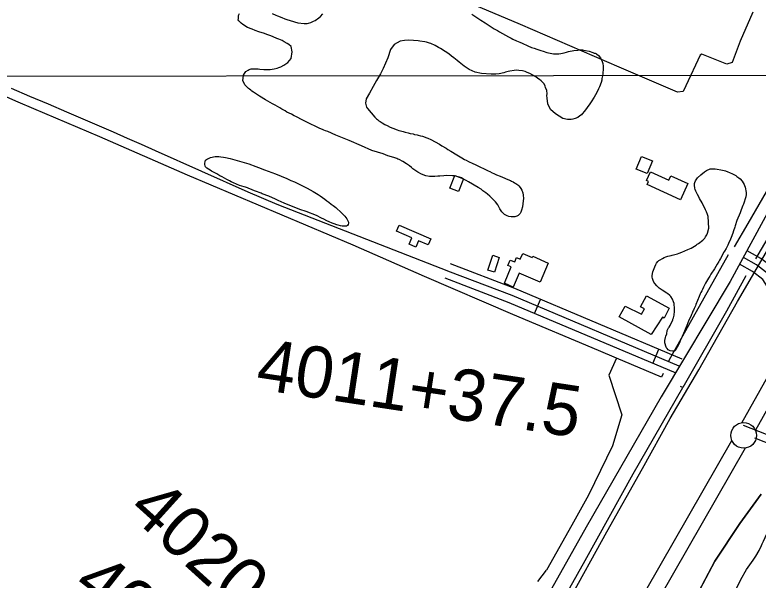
# Model space of a CAD drawing. Extents: x 3297735 to 3335592, y 670436 to 695807.
# Drawn here: x 3313752 to 3315202, y 689991 to 691094 of the extents above; entities that cross this region are included whole.
import ezdxf

# ---------------------------------------------------------------- set-up
doc = ezdxf.new("R2010")
doc.units = 0
for name, color, linetype in [('V-BLDG-OTLN', 7, 'Continuous'), ('V-DTCH-CNTR', 7, 'Continuous'), ('V-GRID-MAJR', 7, 'Continuous'), ('V-LEVE-TOET', 7, 'Continuous'), ('V-ROAD-CNTR', 7, 'Continuous'), ('V-SITE-VEGE', 7, 'Continuous'), ('V-SURV-IDEN', 7, 'Continuous'), ('V-SURV-LINE', 7, 'Continuous'), ('V-TOPO-SHOR', 7, 'Continuous'), ('V-WETL-SWMP', 7, 'Continuous')]:
    doc.layers.add(name, color=color, linetype=linetype)

msp = doc.modelspace()

# ---------------------------------------------------------------- linework, layer by layer
at = {"layer": 'V-BLDG-OTLN'}
for points in [[(3314964.3, 690793.1), (3314974.4, 690817.9), (3314995.9, 690809.1), (3314985.8, 690784.3)], [(3314627.4, 690773.9), (3314617.7, 690749.5), (3314600.7, 690756.2), (3314610.4, 690780.6)], [(3315050.6, 690733.5), (3314985.4, 690763), (3314988.1, 690768.8), (3314984.1, 690770.6), (3314992, 690788.1), (3315027.8, 690771.8), (3315031.5, 690780), (3315064.8, 690764.9)], [(3314501.7, 690683.8), (3314563.7, 690657.1), (3314558.6, 690645.2), (3314539.6, 690653.3), (3314534.4, 690641), (3314521, 690646.8), (3314526.3, 690659), (3314496.6, 690671.8)], [(3314674.8, 690595.8), (3314684.2, 690625), (3314696.7, 690621), (3314687.4, 690591.8)], [(3314792.4, 690609.9), (3314776.8, 690572.9), (3314735.7, 690590.2), (3314724.3, 690563.1), (3314707, 690570.4), (3314720.5, 690602.5), (3314713.9, 690605.3), (3314718.4, 690615.8), (3314727.2, 690612), (3314730.9, 690620.8), (3314738, 690617.7), (3314742.7, 690628.6), (3314761, 690620.8), (3314762.2, 690623.6)], [(3314993.6, 690470.7), (3314931.1, 690505), (3314942.4, 690526), (3314974.7, 690509.9), (3314980.5, 690520.5), (3314972.7, 690524.6), (3314984.4, 690546), (3315028.6, 690522), (3315018.6, 690502.6), (3315015.2, 690504.3)]]:
    msp.add_lwpolyline(points, close=True, dxfattribs=at)
at = {"layer": 'V-DTCH-CNTR'}
for points in [[(3314925.9, 690424.1), (3314910.5, 690391.2), (3314935.8, 690313.8), (3314918.1, 690253.3), (3314870.9, 690157.4), (3314838.3, 690098.4), (3314789, 690010.9)], [(3314772.2, 689988.7), (3314789, 690010.9)]]:
    msp.add_lwpolyline(points, dxfattribs=at)
at = {"layer": 'V-GRID-MAJR'}
msp.add_lwpolyline([(3301853.1, 690965.8), (3302673.5, 690966.2), (3305673.7, 690968.2), (3310110.3, 690971.5), (3313525.5, 690974.4), (3317355.7, 690978.1), (3321058.1, 690982), (3323164.5, 690984.4), (3326643.7, 690988.7), (3330122.8, 690993.3), (3332835.9, 690997.1), (3333379.4, 690997.9)], dxfattribs=at)
at = {"layer": 'V-LEVE-TOET'}
for points in [[(3314907.1, 690085.8), (3314976.7, 690209.3), (3315030.4, 690306.7), (3315086.4, 690401.8), (3315161.6, 690535), (3315227.4, 690647.1), (3315287.9, 690759.3), (3315343.6, 690858.4), (3315397.6, 690945.4), (3315463.7, 691059.5), (3315520.4, 691145.2), (3315573.3, 691212.4), (3315648.7, 691305.4), (3315744.4, 691421.5), (3315825.6, 691528.8), (3315860, 691571.4)], [(3315207.9, 690159.2), (3315166.1, 690101.6), (3315117.4, 690028.3)], [(3314100.4, 689022.4), (3314111.6, 689037.4), (3314125.1, 689067.9), (3314153.7, 689108.7), (3314193.6, 689148.5), (3314273.3, 689221.9), (3314369, 689302.1), (3314457.5, 689375.3), (3314528.4, 689444.5), (3314572, 689497.3), (3314613.1, 689559.8), (3314664.2, 689653.7), (3314725.2, 689763.3), (3314783.5, 689866.7), (3314830.9, 689947.5), (3314907.1, 690085.8)], [(3315117.4, 690028.3), (3315058.4, 689916.5), (3314990.5, 689797), (3314920.8, 689673.1), (3314848.5, 689549.2), (3314768.2, 689413.2), (3314704.3, 689329.4), (3314636.1, 689250), (3314540.5, 689150), (3314446.3, 689084), (3314346.7, 689010.3), (3314299.8, 688961.1), (3314258, 688900.6), (3314223.3, 688846.9), (3314181.3, 688776.8), (3314158.1, 688736.1), (3314134.7, 688678.8), (3314082.7, 688587.9)]]:
    msp.add_lwpolyline(points, dxfattribs=at)
at = {"layer": 'V-ROAD-CNTR'}
for p, q in [((3314766, 690511.4), (3314777.7, 690539)), ((3314996.3, 690414.2), (3315008, 690441.9))]:
    msp.add_line(p, q, dxfattribs=at)
for points in [[(3314598.5, 690593.7), (3314263.8, 690724), (3314207, 690748.3), (3314026.3, 690828.8), (3313999.1, 690840.9), (3313971.9, 690852.9), (3313944.6, 690864.9), (3313917.2, 690876.7), (3313889.8, 690888.4), (3313853.8, 690904.1), (3313817.7, 690919.6), (3313781.6, 690935), (3313745.4, 690950.2)], [(3315256.1, 690773.3), (3315147.7, 690573.9), (3315012.5, 690349.2), (3314866.5, 690094.8), (3314702, 689802.1)], [(3315284.2, 690514.2), (3315282.2, 690518.3), (3315265.2, 690548), (3315253.6, 690567), (3315233.7, 690598.5), (3315207.4, 690618.7), (3315180.6, 690633.9)], [(3315277.4, 690494), (3315268.9, 690511.3), (3315252.3, 690540.4), (3315240.9, 690559.1), (3315222.5, 690588.3), (3315199.1, 690606.2), (3315173.2, 690620.9)], [(3315054.1, 690422.4), (3314727.5, 690560.2), (3314602, 690608.3)], [(3315264, 690487.4), (3315255.7, 690504.2), (3315239.4, 690532.8), (3315228.1, 690551.2), (3315211.2, 690578), (3315190.8, 690593.7), (3315165.8, 690607.8)], [(3315048.2, 690408.6), (3314721.9, 690546.3), (3314596.6, 690594.3)], [(3315042.4, 690394.8), (3314716.3, 690532.4), (3314591.2, 690580.3)], [(3316183.2, 689553.8), (3315934.9, 689765.3), (3315796.5, 689871.4), (3315695.2, 689937.6), (3315638.5, 689975.3), (3315597.6, 689993.4), (3315531.1, 690029.3), (3315471.3, 690048.8), (3315425.9, 690064.2), (3315389.8, 690079.3), (3315353.1, 690097.3), (3315316.7, 690156.3), (3315296.6, 690194.5), (3315281.4, 690234.8), (3315271.3, 690251.9), (3315251.4, 690262.2), (3315173.6, 690292.9)], [(3315235.3, 690252.4), (3315195.8, 690268)]]:
    msp.add_lwpolyline(points, dxfattribs=at)
at = {"layer": 'V-SITE-VEGE'}
for points in [[(3314242.9, 690987.3), (3314246.6, 690987.3), (3314250.2, 690987.5), (3314258.1, 690988.8), (3314263.6, 690990.1), (3314267.3, 690991.1), (3314270.7, 690992.4), (3314277, 690996.1), (3314282.7, 691000), (3314284.8, 691001.3), (3314291.1, 691008.8), (3314293.3, 691021.9), (3314291, 691032.1), (3314286.5, 691036.1), (3314283.4, 691038.4), (3314277.7, 691041.6), (3314273.5, 691043.7), (3314267.2, 691046.6), (3314263, 691048.2), (3314256.2, 691051.1), (3314251.3, 691053), (3314243.7, 691055.6), (3314239, 691057.4), (3314227.7, 691061.2), (3314220.9, 691063.5), (3314214.9, 691065.9), (3314206, 691069.6), (3314196.9, 691075.1), (3314193.5, 691077.8), (3314188.8, 691082.5), (3314187.5, 691084.6), (3314188.1, 691087.2), (3314188.1, 691089.8), (3314188.6, 691093), (3314190.2, 691096.6)], [(3314253.8, 691096.4), (3314261.1, 691093.7), (3314264.5, 691092.2), (3314273.1, 691088.7), (3314278.6, 691086.4), (3314282.8, 691085), (3314289.1, 691082.7), (3314304.2, 691078.7), (3314316.2, 691077.3), (3314322.3, 691077.3), (3314325.2, 691077.8), (3314329.3, 691079.1), (3314334.6, 691081.4), (3314337.7, 691083), (3314344.8, 691088), (3314348, 691090.6), (3314352.7, 691095.8)], [(3314643.7, 691095.5), (3314647.6, 691092.9), (3314660.9, 691083.9), (3314669.5, 691078.4), (3314681.3, 691070.5), (3314685.2, 691068.2), (3314686.8, 691066.8), (3314693.3, 691063.2)], [(3314693.3, 691063.2), (3314697.7, 691060.8), (3314703.2, 691057.6), (3314715, 691051.3), (3314720.2, 691048.7), (3314723.6, 691046.8), (3314730.7, 691043.4), (3314736.9, 691040.5), (3314741.4, 691038.7), (3314752.6, 691033.4), (3314760.2, 691030.5), (3314765.1, 691028.9), (3314770.4, 691027), (3314778, 691024.7), (3314782.9, 691023.3), (3314790, 691020.9), (3314803.1, 691018), (3314809.1, 691018), (3314813.3, 691018.2), (3314817.2, 691018.8), (3314823.5, 691020), (3314827.9, 691021.1), (3314831.9, 691022.4), (3314835.5, 691023.4), (3314838.9, 691023.9), (3314842.3, 691024.7), (3314850.2, 691025.4), (3314854.1, 691025.7), (3314859.3, 691025.7), (3314861.4, 691025.4), (3314865.1, 691024.6), (3314872.4, 691023.3), (3314879.7, 691020.9), (3314882.4, 691019.6), (3314884.4, 691019), (3314886.5, 691017.7), (3314890.7, 691014.6), (3314894.4, 691010.1), (3314895.9, 691007), (3314897.2, 691004.9), (3314899, 690999.4), (3314899.8, 690993.6), (3314899.8, 690989.2), (3314899, 690978.9), (3314898.2, 690975), (3314897.9, 690972.4), (3314897.4, 690970.1), (3314896.8, 690966.9), (3314895.5, 690962), (3314892.6, 690953.8), (3314890.5, 690949.7), (3314887.3, 690942.6), (3314884.9, 690938.2), (3314882.3, 690933.7), (3314876, 690924.1), (3314873.9, 690920.4), (3314863.4, 690906.1), (3314858.9, 690900.8), (3314857.1, 690899), (3314854.4, 690896.9), (3314850.2, 690894.1), (3314845, 690892), (3314840.5, 690890.4), (3314837.4, 690889.7), (3314829.8, 690890), (3314820.9, 690891.8), (3314806.6, 690900.8), (3314797.2, 690909.7), (3314791.5, 690920.7), (3314790.7, 690931.2), (3314789.9, 690936.9), (3314790.2, 690940.1), (3314789.5, 690946.4), (3314787.1, 690952.4), (3314786.3, 690954.7), (3314784.5, 690959.2), (3314783.2, 690960.8), (3314778.8, 690965.2), (3314775.4, 690968.1), (3314772.5, 690970), (3314768.4, 690972.9), (3314756.6, 690979.5), (3314751.4, 690981.8), (3314747.5, 690983.2), (3314742.2, 690984.5), (3314735.2, 690985.6), (3314731.2, 690985.8), (3314726, 690985.3), (3314717.4, 690984), (3314714.2, 690983.3), (3314709.2, 690982.2), (3314706.1, 690980.9), (3314696.7, 690979.1), (3314690.6, 690978.4), (3314685.9, 690978.1), (3314681, 690978.2), (3314662.4, 690979.3), (3314650.1, 690982.5), (3314638.6, 690987.7), (3314628.4, 690994), (3314619, 691001.7)], [(3314619, 691001.7), (3314614.8, 691004.8), (3314608.3, 691010.3), (3314603.9, 691013.5), (3314598.4, 691018), (3314591.4, 691022.7), (3314582.5, 691028.2), (3314578.3, 691030.6), (3314571.8, 691034), (3314563.7, 691038), (3314561.1, 691039), (3314557.1, 691040.4), (3314554.8, 691040.9), (3314551.9, 691041.7), (3314542, 691043), (3314538.8, 691043.3), (3314520.3, 691044.4), (3314511.9, 691043.9), (3314503.5, 691042.6), (3314492, 691036.4), (3314485.1, 691026.2), (3314479.6, 691010), (3314470.7, 690989.5), (3314465.6, 690978.9), (3314457.4, 690965.9), (3314450.8, 690954.4), (3314443.7, 690941.1), (3314437.4, 690930.3), (3314436.3, 690922), (3314438.1, 690913.9), (3314440.2, 690911.2), (3314454.6, 690894.4), (3314457.4, 690891.5), (3314459.5, 690890), (3314462.4, 690887.3), (3314464.7, 690885.8), (3314468.4, 690883.7), (3314473.9, 690880.2), (3314478.3, 690877.9), (3314484.1, 690875), (3314489.3, 690872.8), (3314497.9, 690869.7), (3314501.1, 690868.6), (3314504.2, 690867.8), (3314509.4, 690866.2), (3314513.6, 690865.2), (3314519.6, 690863.8), (3314523.5, 690862.8), (3314528.8, 690862), (3314531.9, 690860.9), (3314536.6, 690860.1), (3314539, 690859.6), (3314543.1, 690858.3), (3314547.1, 690857.2), (3314556, 690854.3), (3314558, 690853.2), (3314563.5, 690850.9), (3314580.5, 690841.6), (3314585, 690838.7), (3314593.6, 690834), (3314596.4, 690831.6), (3314602.4, 690828), (3314614.5, 690821.1), (3314620.5, 690817.2), (3314623.9, 690815.3), (3314629.3, 690811.9), (3314632.2, 690810.6), (3314636.7, 690808.2), (3314645.3, 690804.3), (3314649.7, 690801.9), (3314652.9, 690800.6), (3314657.8, 690798.2), (3314660.7, 690796.6), (3314666.2, 690794.2), (3314675.1, 690789.8), (3314678.5, 690788.4), (3314683.4, 690786.1), (3314686.6, 690784.7), (3314691.5, 690782.1), (3314698.8, 690779.2), (3314703, 690777.4), (3314713.7, 690773.1), (3314718.7, 690771), (3314720.8, 690769.7), (3314724.4, 690768.1), (3314726.8, 690766.5), (3314729.4, 690765), (3314733.1, 690762.3), (3314735.1, 690760.5), (3314737.8, 690757.3), (3314739.3, 690755.2), (3314740.9, 690752.1), (3314742.7, 690746.6), (3314743.5, 690742.4), (3314744, 690735.6), (3314743.7, 690731.4), (3314742.6, 690719.4), (3314740.7, 690713.1), (3314739.4, 690709.4), (3314738.1, 690706.8), (3314735.5, 690703.7)], [(3314735.5, 690703.7), (3314733.6, 690702.4), (3314731, 690701.4), (3314727.1, 690700.3), (3314723.7, 690699.8), (3314720.3, 690699.8), (3314715.6, 690700.6), (3314712.7, 690701.7), (3314706.9, 690704.8), (3314704.6, 690707.2), (3314702, 690710.1), (3314700.7, 690711.9), (3314698.4, 690715.6), (3314693.9, 690723.2), (3314689.5, 690729.3), (3314686.4, 690732.7), (3314681.9, 690737.1), (3314678.5, 690740.3), (3314673.9, 690744.2), (3314670.5, 690746.9), (3314665, 690750.8), (3314661.6, 690753.7), (3314656.1, 690757.4), (3314637.3, 690768.4), (3314632.6, 690770.8), (3314625.5, 690774.8), (3314623.5, 690775.8), (3314619.5, 690777.4), (3314616.9, 690778.2), (3314609.9, 690779.8), (3314605.7, 690780.3), (3314594.4, 690780.4), (3314588.9, 690779.9), (3314581.1, 690779.6), (3314577.1, 690779.4), (3314571.6, 690778.6), (3314560.7, 690778.6), (3314553.9, 690780), (3314545.5, 690783.1), (3314538.2, 690787.1), (3314534.3, 690789.5), (3314528.5, 690793.9), (3314525.7, 690796), (3314521.7, 690799.2), (3314516, 690803.4), (3314508.7, 690807.9), (3314501.9, 690811.6), (3314499.3, 690812.6), (3314496.9, 690813.9), (3314493.5, 690815), (3314491.4, 690815.5), (3314479.9, 690819.2), (3314470.5, 690822.7), (3314448.6, 690829.6), (3314428.5, 690838.8), (3314404.2, 690848.6), (3314378.3, 690859.4), (3314362.3, 690866.2), (3314358.2, 690867.8), (3314355, 690868.9), (3314352.2, 690870.5), (3314347.2, 690872.6), (3314339.1, 690876.3), (3314327.9, 690881.5), (3314314, 690888.7), (3314299.9, 690895.5), (3314296.8, 690897.1), (3314291.8, 690900), (3314282.9, 690904.5), (3314279.3, 690906.8), (3314273, 690910), (3314269.1, 690912.6), (3314259.7, 690917.9), (3314254.5, 690920.5), (3314241.1, 690928.4), (3314238, 690930.5), (3314232.8, 690933.4), (3314229.4, 690935.5), (3314225.2, 690938.2), (3314219.7, 690941.8), (3314217.4, 690943.2), (3314214.2, 690945.3), (3314212.4, 690946.8), (3314209.5, 690948.9), (3314207.7, 690950.5), (3314200.7, 690957.6), (3314199.1, 690960.5), (3314197, 690965), (3314197.9, 690976.2), (3314200, 690979.9), (3314202.9, 690983.3), (3314207.1, 690986.4), (3314209.4, 690987.4), (3314213.1, 690988.7), (3314215.2, 690988.7), (3314218.6, 690989), (3314222.8, 690988.9), (3314226.4, 690988.4), (3314229.8, 690988.1), (3314237.7, 690987.1), (3314242.9, 690987.3)], [(3315006.5, 690563.8), (3315004.4, 690565.7), (3315000.5, 690570.3), (3314998.8, 690572.7), (3314996.9, 690576), (3314995.7, 690579.6), (3314995.1, 690582.1), (3314995.1, 690585.4), (3314996.6, 690592.8), (3315000.6, 690602.8), (3315002.5, 690607), (3315004, 690609.5), (3315006.3, 690613), (3315008.2, 690614.7), (3315010.7, 690615.9), (3315015.3, 690618.9), (3315018.7, 690620.7), (3315021.6, 690622), (3315025.8, 690623.2), (3315032.1, 690624.5), (3315034.6, 690625.3), (3315044.6, 690627.8), (3315048, 690629), (3315053, 690631.3), (3315064.6, 690636.1), (3315071.3, 690639.2), (3315080.9, 690644.8), (3315083.2, 690646.5), (3315085.5, 690647.7), (3315094.1, 690654.2), (3315095.6, 690655.6), (3315098.1, 690658.6), (3315099.6, 690660.9), (3315101.9, 690665), (3315103.2, 690668.2), (3315105.7, 690677.6), (3315104.4, 690700.4), (3315103.3, 690704.4), (3315101.3, 690710), (3315099.6, 690714), (3315092.7, 690727.5), (3315087.7, 690735.8), (3315086.3, 690738.8), (3315083.8, 690743.4), (3315080.7, 690750.1), (3315079.4, 690753.5), (3315078.8, 690756), (3315077.8, 690762), (3315077.8, 690765.2), (3315078.2, 690767.3), (3315079.5, 690770.4), (3315081.4, 690772.5), (3315083.9, 690775.8), (3315090, 690781.9), (3315097.3, 690787.9), (3315101.1, 690790.4), (3315108.7, 690793.6), (3315116.2, 690793.9), (3315118.3, 690793.7), (3315122.3, 690793.1), (3315129.4, 690791.6), (3315135.9, 690790.1), (3315138.2, 690789.5), (3315143, 690787.8), (3315146.3, 690786.3), (3315152, 690783.6), (3315154.7, 690782.5), (3315158.2, 690780.4), (3315160.7, 690778.7), (3315164.3, 690776), (3315166.6, 690773.9), (3315170.8, 690769.3), (3315172.8, 690766.5), (3315174.7, 690763.2), (3315175.3, 690760.9), (3315176.4, 690758.1)], [(3315176.4, 690758.1), (3315177.4, 690754.8), (3315178.2, 690751), (3315178.4, 690747.5), (3315178.4, 690743.9), (3315177.8, 690739.1), (3315176.9, 690735.1), (3315174.6, 690728.4), (3315173.5, 690724.9), (3315172.3, 690721.9), (3315169.1, 690713.4), (3315166.6, 690707.9), (3315160.4, 690692.9), (3315157.1, 690682.4), (3315156.4, 690679.9), (3315154.1, 690673), (3315152.4, 690668.2), (3315149.2, 690660), (3315148, 690656.3), (3315144.2, 690647.9), (3315142.9, 690644.8), (3315141.6, 690642.3), (3315139.5, 690638.5), (3315136.1, 690632.9), (3315134.5, 690630.4), (3315130.9, 690623.1), (3315128.4, 690618.5), (3315126.9, 690615.5), (3315125, 690612.6), (3315122.2, 690607.8), (3315116.6, 690598.4), (3315110, 690588.4), (3315107.5, 690584.2), (3315105, 690580.6), (3315102.9, 690577.1), (3315099.3, 690570.6), (3315095.7, 690563.1), (3315093.2, 690558.5), (3315092.1, 690556), (3315090.2, 690552.2), (3315089.2, 690549.5), (3315087.1, 690544.7), (3315080.5, 690529), (3315079.7, 690526.5), (3315077.1, 690521.1), (3315075.9, 690517.9), (3315074.8, 690515.9), (3315073.3, 690512.3), (3315072.1, 690509.6), (3315070.4, 690505.4), (3315067.6, 690500), (3315064.9, 690493.3), (3315064, 690491), (3315059.6, 690480.3), (3315058.1, 690477.2), (3315051.8, 690461.9), (3315049.9, 690458.2), (3315048.4, 690454.4), (3315044.2, 690445.6), (3315042.7, 690442.9), (3315041.5, 690440.8), (3315039.6, 690438.9), (3315037.3, 690438.1), (3315035.2, 690437.9), (3315030.6, 690438.8), (3315026.6, 690440.9), (3315024.5, 690443), (3315023.3, 690444.6), (3315021.8, 690447.6), (3315020.6, 690452.2), (3315020.2, 690454.5), (3315020.2, 690459.1), (3315021, 690464.8), (3315021.9, 690467.5), (3315023.6, 690471.7), (3315024.6, 690478.3), (3315027.2, 690483.2), (3315028.6, 690485), (3315030.3, 690488), (3315032.4, 690492.8), (3315035.4, 690498.4), (3315035.8, 690500.5), (3315036.9, 690503.2), (3315037.9, 690508.4), (3315038.6, 690516), (3315038.8, 690520.2), (3315038.8, 690523.5), (3315038.4, 690527.9), (3315038, 690530.8), (3315037.2, 690534.4), (3315034.9, 690539.4), (3315031.4, 690544.7), (3315029.5, 690546.6), (3315024.9, 690550.6), (3315022.8, 690552), (3315020.1, 690553.5), (3315014.7, 690557.1), (3315012.8, 690558.2), (3315010.9, 690559.6), (3315009.2, 690561.1), (3315006.5, 690563.8)], [(3315125, 689905.5), (3315168.2, 689992.6), (3315179.4, 690011.8), (3315192.5, 690030), (3315197.4, 690037.8), (3315203.8, 690049.4), (3315208.7, 690059.1), (3315210.1, 690062.4), (3315212.7, 690067.2), (3315218.9, 690081.6), (3315220.9, 690086.2), (3315222.1, 690089.5), (3315224, 690094.2), (3315225.6, 690097.5), (3315230.9, 690107.2), (3315234.6, 690113.2), (3315236.9, 690116.1), (3315239.1, 690118), (3315242.4, 690121.3), (3315244.7, 690123.4), (3315246.8, 690125.2), (3315251.1, 690127.7), (3315253.1, 690128.3), (3315258.5, 690128.8)]]:
    msp.add_lwpolyline(points, dxfattribs=at)
msp.add_lwpolyline([(3314142.9, 690817.7), (3314145.4, 690817.7), (3314150, 690817.5), (3314153.6, 690817), (3314159.2, 690816.2), (3314162.8, 690815.8), (3314172, 690813.8), (3314176.6, 690812.8), (3314208.2, 690803.2), (3314222.4, 690798.2), (3314227.4, 690796.5), (3314239.3, 690791.8), (3314260.4, 690783.8), (3314282.6, 690774.5), (3314286.4, 690773), (3314290.5, 690770.9), (3314297.4, 690768), (3314322.1, 690755.7), (3314333.8, 690749.4), (3314343.6, 690743.5), (3314347.4, 690741), (3314357, 690734.3), (3314360.5, 690731.5), (3314364.3, 690728.8), (3314369.3, 690724.8), (3314372.7, 690722.3), (3314377.9, 690718.1), (3314389.4, 690708), (3314395.8, 690701.5), (3314399.8, 690696.4), (3314401.2, 690693.5), (3314402.9, 690689.7), (3314402.9, 690687.4), (3314402.5, 690685.1), (3314401.2, 690683.2), (3314398.7, 690682), (3314396.6, 690681.8), (3314390.7, 690681.8), (3314387.6, 690682.2), (3314382.6, 690683.5), (3314380.1, 690684.3), (3314375, 690686.2), (3314371.3, 690687.9), (3314365, 690690.5), (3314360.8, 690692.4), (3314354.6, 690695.5), (3314350.4, 690697.4), (3314340.3, 690702.3), (3314320.5, 690710.5), (3314308.1, 690714.5), (3314300.2, 690717.9), (3314282.2, 690724.9), (3314277.6, 690727), (3314265.9, 690731.9), (3314259, 690735), (3314254.4, 690736.9), (3314247.3, 690740.3), (3314234.8, 690745.2), (3314232.3, 690746), (3314221.8, 690750.4), (3314216.4, 690752.3), (3314213.4, 690753.6), (3314208.6, 690755.3), (3314205.7, 690756.6), (3314201.9, 690757.6), (3314199.6, 690758.5), (3314190.2, 690761), (3314178.5, 690766.1), (3314174.1, 690768.4), (3314170.8, 690770.3), (3314165.4, 690773), (3314156.2, 690778.1), (3314152.2, 690780), (3314145.9, 690783.8), (3314135.7, 690789.3), (3314132.8, 690790.9), (3314129.8, 690792.8), (3314126.7, 690795.2), (3314124.2, 690797.7), (3314123.2, 690799.8), (3314122.5, 690802.3), (3314122.6, 690805), (3314123.2, 690807.5), (3314124.2, 690810.4), (3314125.7, 690812.1), (3314128, 690812.9), (3314129.9, 690814), (3314133.9, 690815.6)], close=True, dxfattribs=at)
at = {"layer": 'V-SURV-LINE'}
for points in [[(3315170.4, 690298.5), (3315611.8, 691084.8)], [(3315637.9, 691070.1), (3315196.6, 690283.8)], [(3314705.9, 689487.8), (3315150.8, 690263.9)], [(3315176.8, 690249), (3314731.9, 689472.9)]]:
    msp.add_lwpolyline(points, dxfattribs=at)
msp.add_circle((3315173.7, 690273.7), 25, dxfattribs=at)
at = {"layer": 'V-TOPO-SHOR'}
for p, q in [((3315013.3, 690387.1), (3314925.9, 690424.1)), ((3315016.7, 690394.7), (3315013.3, 690387.1))]:
    msp.add_line(p, q, dxfattribs=at)
for points in [[(3315191.5, 691099.3), (3315166.8, 691042.9), (3315151, 691001.3), (3315141, 690998), (3315092.4, 691017.1), (3315088.6, 691015.3), (3315060.9, 690955.6), (3315055.7, 690944.4), (3315044.9, 690943), (3314930.6, 690992.1), (3314738.4, 691074.9), (3314672.3, 691103.2), (3314609.7, 691130), (3314458.3, 691195.5), (3314440.9, 691199.7), (3314414.1, 691208), (3314279.8, 691264.2), (3314119.2, 691335.7), (3313963, 691403.2), (3313837.2, 691456.4), (3313671.4, 691529.8), (3313540.2, 691587.3), (3313525.2, 691593.8)], [(3313758.6, 690923.8), (3313653.9, 690969.7), (3313499.9, 691036.4), (3313339.3, 691106.1), (3313176, 691176.5), (3313031, 691238.4), (3312853.6, 691315.2), (3312692.6, 691383), (3312525.3, 691456.4), (3312372.8, 691523.5)], [(3315197.6, 690618.4), (3315272, 690745.3), (3315351.6, 690888.8), (3315427.9, 691023), (3315470.9, 691088.3), (3315502.3, 691135.3), (3315537.3, 691182.8), (3315602.3, 691266.2), (3315652.7, 691327.7), (3315709.8, 691395.8), (3315746.4, 691440.7)], [(3314925.9, 690424.1), (3314890.5, 690439.5), (3314723.2, 690509.2), (3314551, 690583.4), (3314412.3, 690644.5), (3314227.5, 690722.8), (3314089.1, 690781.6), (3313917.7, 690855.8), (3313788.9, 690910.5), (3313758.6, 690923.8)], [(3315267.3, 690836.5), (3315232.2, 690773.5), (3315182.1, 690686.7), (3315155.5, 690641.8)], [(3315143.2, 690625.9), (3315028, 690420.1), (3315026.4, 690416.4)], [(3315178.1, 690585.1), (3315140.4, 690515.7), (3315055.1, 690367), (3315050.8, 690369.1)], [(3314864.4, 690029.9), (3314957.9, 690198.7), (3315055.1, 690367)], [(3314118.4, 689071.5), (3314168.8, 689135.4), (3314245.8, 689205.2), (3314370.2, 689315.9), (3314433.7, 689373.5), (3314485.7, 689426.8), (3314544, 689488.8), (3314576.4, 689528.2), (3314617, 689592.3), (3314668.7, 689685.4), (3314769.1, 689859.2), (3314864.4, 690029.9)]]:
    msp.add_lwpolyline(points, dxfattribs=at)
at = {"layer": 'V-WETL-SWMP'}
for p, q in [((3315166.1, 690101.6), (3315207.9, 690159.2)), ((3315117.5, 690028.3), (3315166.1, 690101.6)), ((3315058.4, 689916.5), (3315117.5, 690028.3))]:
    msp.add_line(p, q, dxfattribs=at)

# ---------------------------------------------------------------- texts
at = {"layer": 'V-SURV-IDEN'}
for s, rotation, p in [('4011+37.5', 351.3694, (3314219.9, 690364.6)), ('4020+72.0', 317.891, (3313969, 690123.3)), ('4021+72.8', 321.8315, (3313861, 689973.4))]:
    msp.add_text(s, height=100, rotation=rotation, dxfattribs=at).set_placement(p)

doc.saveas('drawing.dxf')
